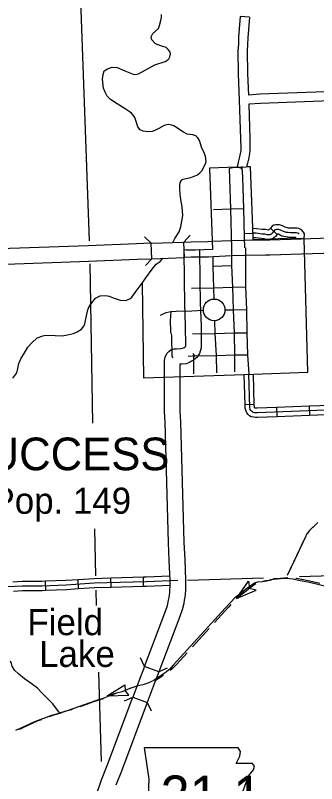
# Model space of a CAD drawing. Extents: x 1164457 to 1439835, y 1590918 to 1773502.
# Drawn here: x 1254222 to 1259097, y 1641151 to 1653578 of the extents above; entities that cross this region are included whole.
import ezdxf

# ---------------------------------------------------------------- set-up
doc = ezdxf.new("R2010")
doc.units = 0
for name, color, linetype in [('Level 10', 7, 'Continuous'), ('Level 21', 7, 'Continuous'), ('Level 24', 7, 'Continuous'), ('Level 32', 7, 'Continuous'), ('Level 33', 7, 'Continuous'), ('Level 34', 7, 'Continuous'), ('Level 35', 7, 'Continuous'), ('Level 37', 7, 'Continuous'), ('Level 43', 7, 'Continuous'), ('Level 46', 7, 'Continuous'), ('Level 5', 7, 'Continuous'), ('Level 6', 7, 'Continuous')]:
    doc.layers.add(name, color=color, linetype=linetype)

msp = doc.modelspace()

# ---------------------------------------------------------------- linework, layer by layer
at = {"layer": 'Level 10'}
for points in [[(1256950, 1649910), (1257059, 1649914), (1257336, 1649919), (1257412, 1649923), (1257714, 1649937), (1257929, 1649944), (1257942, 1649944), (1258271, 1649948), (1258338, 1649949), (1258846, 1649963), (1260259, 1650010), (1260740, 1650032), (1263418, 1650108), (1264752, 1650155), (1264828, 1650158), (1264837, 1649908)], [(1256431, 1649642), (1256422, 1649892), (1256182, 1649884), (1255399, 1649852), (1252701, 1649756)], [(1256422, 1649892), (1256950, 1649910)], [(1264837, 1649908), (1264761, 1649905), (1263426, 1649858), (1260749, 1649782), (1260269, 1649760), (1258853, 1649713), (1258342, 1649699), (1258274, 1649699), (1257944, 1649694), (1257933, 1649694), (1257724, 1649688), (1257425, 1649674), (1257345, 1649669), (1257066, 1649664), (1256958, 1649660), (1256950, 1649910)], [(1256832, 1648186), (1256904, 1648189), (1256945, 1648198), (1256952, 1648203), (1256962, 1648207), (1256970, 1648215), (1256976, 1648223), (1256981, 1648239), (1256977, 1648549), (1256965, 1648923), (1256957, 1649291), (1256952, 1649787), (1257202, 1649790)], [(1257202, 1649790), (1257207, 1649295), (1257215, 1648929), (1257227, 1648554), (1257231, 1648201), (1257201, 1648108), (1257157, 1648046), (1257102, 1647998), (1257073, 1647984), (1257041, 1647964), (1256988, 1647940)], [(1252710, 1649506), (1255408, 1649602), (1256191, 1649634), (1256431, 1649642)], [(1256431, 1649642), (1256958, 1649660)], [(1256309, 1643046), (1256650, 1643939), (1256682, 1644030), (1256701, 1644116), (1256710, 1644161), (1256716, 1644199), (1256721, 1644245), (1256724, 1644285), (1256725, 1644338), (1256725, 1644439), (1256712, 1644767), (1256699, 1645044), (1256644, 1646995), (1256635, 1647167), (1256635, 1647938), (1256636, 1647997), (1256644, 1648047), (1256671, 1648106), (1256703, 1648141), (1256739, 1648168), (1256798, 1648183), (1256832, 1648186)], [(1256988, 1647940), (1256916, 1647937), (1256885, 1647936), (1256885, 1647174), (1256893, 1647005), (1256949, 1645053), (1256962, 1644778), (1256975, 1644444), (1256975, 1644335), (1256974, 1644275), (1256970, 1644223), (1256964, 1644165), (1256956, 1644117), (1256946, 1644064), (1256923, 1643961), (1256884, 1643853), (1256543, 1642957), (1256309, 1643046)], [(1256309, 1643046), (1256218, 1642808), (1256122, 1642551)], [(1256543, 1642957), (1256452, 1642720), (1256356, 1642464)], [(1255613, 1641211), (1255708, 1641443), (1256122, 1642551), (1256356, 1642464)], [(1256356, 1642464), (1255941, 1641352), (1255847, 1641124)], [(1255933, 1634192), (1255683, 1634177), (1255683, 1634182), (1255613, 1636388), (1255540, 1639052), (1255523, 1639608), (1255507, 1640363), (1255498, 1640706), (1255500, 1640783), (1255507, 1640833), (1255508, 1640838), (1255509, 1640872), (1255535, 1640977), (1255613, 1641211)]]:
    msp.add_lwpolyline(points, dxfattribs=at)
at = {"layer": 'Level 21'}
msp.add_lwpolyline([(1256307, 1641730), (1256383, 1641222), (1256349, 1640452), (1256417, 1640410), (1256544, 1640410), (1256544, 1640139), (1257610, 1640139), (1257661, 1640249), (1257644, 1640427), (1257669, 1640630), (1257762, 1640791), (1257821, 1640909), (1257906, 1641036), (1257957, 1641171), (1257999, 1641281), (1258075, 1641374), (1258092, 1641434), (1258058, 1641476), (1257796, 1641476), (1257855, 1641594), (1257864, 1641670), (1257829, 1641729)], close=True, dxfattribs=at)
at = {"layer": 'Level 24'}
msp.add_circle((1257439, 1648813), 175, dxfattribs=at)
at = {"layer": 'Level 32'}
for p, q in [((1258348, 1650138), (1258457, 1650035)), ((1258897, 1649964), (1258762, 1649961)), ((1258088, 1647284), (1257938, 1647280)), ((1258446, 1647234), (1258452, 1647084)), ((1258974, 1647254), (1258980, 1647104)), ((1255770, 1644330), (1255766, 1644480)), ((1256298, 1644345), (1256294, 1644495)), ((1254716, 1644280), (1254710, 1644430)), ((1255245, 1644305), (1255236, 1644455))]:
    msp.add_line(p, q, dxfattribs=at)
for points in [[(1258897, 1649964), (1258901, 1650044), (1258887, 1650071), (1258851, 1650106), (1258842, 1650112), (1258829, 1650120), (1258809, 1650128), (1258777, 1650135), (1258753, 1650136), (1258737, 1650136), (1258677, 1650136), (1258644, 1650138), (1258625, 1650141), (1258586, 1650150), (1258544, 1650172), (1258527, 1650179), (1258496, 1650189), (1258461, 1650191), (1258437, 1650189), (1258407, 1650182), (1258379, 1650168), (1258348, 1650138), (1258316, 1650101)], [(1258345, 1649954), (1258330, 1649953), (1258312, 1649952), (1258287, 1649953), (1258250, 1649963), (1258220, 1649964), (1258199, 1649966), (1258111, 1649978), (1258068, 1649979), (1258062, 1650129)], [(1258316, 1650101), (1258272, 1650112), (1258231, 1650114), (1258216, 1650115), (1258123, 1650127), (1258062, 1650129)], [(1258815, 1650038), (1258803, 1650048), (1258801, 1650050), (1258796, 1650053), (1258788, 1650056), (1258768, 1650060), (1258751, 1650061), (1258737, 1650061), (1258675, 1650061), (1258636, 1650063), (1258611, 1650067), (1258560, 1650079), (1258511, 1650104), (1258500, 1650109), (1258482, 1650115), (1258462, 1650116), (1258449, 1650115), (1258433, 1650111), (1258423, 1650106), (1258403, 1650087), (1258375, 1650054), (1258360, 1650038), (1258343, 1650030), (1258323, 1650027), (1258312, 1650027), (1258299, 1650028)], [(1258299, 1650028), (1258261, 1650037), (1258225, 1650039), (1258208, 1650041), (1258117, 1650052), (1258067, 1650054)], [(1258762, 1649961), (1258762, 1649985), (1258759, 1649985), (1258749, 1649986), (1258736, 1649986), (1258673, 1649986), (1258629, 1649988), (1258597, 1649993), (1258534, 1650008), (1258478, 1650037), (1258472, 1650039), (1258469, 1650040), (1258463, 1650041), (1258457, 1650035), (1258431, 1650003), (1258405, 1649977), (1258365, 1649957), (1258345, 1649954)], [(1257938, 1647280), (1257923, 1647771), (1258073, 1647776)], [(1259922, 1647216), (1258140, 1647147), (1258114, 1647147), (1258093, 1647150), (1258069, 1647156), (1258057, 1647164), (1258041, 1647176), (1258033, 1647187), (1258024, 1647202), (1258015, 1647235), (1257998, 1647773)], [(1258088, 1647284), (1258073, 1647776)], [(1258452, 1647084), (1258142, 1647072), (1258109, 1647072), (1258079, 1647076), (1258039, 1647086), (1258013, 1647102), (1257988, 1647123), (1257970, 1647146), (1257955, 1647173), (1257940, 1647224), (1257938, 1647280)], [(1258446, 1647234), (1258137, 1647222), (1258118, 1647222), (1258108, 1647223), (1258099, 1647226), (1258095, 1647229), (1258094, 1647231), (1258089, 1647247), (1258088, 1647284)], [(1258974, 1647254), (1258446, 1647234)], [(1259501, 1647275), (1258974, 1647254)], [(1258980, 1647104), (1258452, 1647084)], [(1259507, 1647125), (1258980, 1647104)], [(1255236, 1644455), (1255495, 1644471), (1255766, 1644480)], [(1255766, 1644480), (1256294, 1644495)], [(1256294, 1644495), (1256338, 1644497), (1256722, 1644512)], [(1251548, 1644222), (1251717, 1644226), (1251976, 1644232), (1253539, 1644311), (1254100, 1644337), (1254336, 1644348), (1254651, 1644352), (1255043, 1644367), (1255498, 1644397), (1256340, 1644422), (1256850, 1644442)], [(1254182, 1644416), (1254334, 1644423), (1254649, 1644427), (1254710, 1644430)], [(1254710, 1644430), (1255039, 1644442), (1255236, 1644455)], [(1255770, 1644330), (1256298, 1644345)], [(1256298, 1644345), (1256343, 1644347), (1256725, 1644362)], [(1254189, 1644266), (1254338, 1644273), (1254653, 1644277), (1254716, 1644280)], [(1254716, 1644280), (1255047, 1644292), (1255245, 1644305)], [(1255245, 1644305), (1255502, 1644322), (1255770, 1644330)]]:
    msp.add_lwpolyline(points, dxfattribs=at)
at = {"layer": 'Level 33'}
for points in [[(1257682, 1651097), (1257703, 1650450), (1257719, 1649812)], [(1257719, 1649812), (1257722, 1649530), (1257736, 1649179), (1257747, 1648814), (1257761, 1648440), (1257770, 1648087)], [(1257419, 1649671), (1257420, 1649519), (1257428, 1649173), (1257433, 1648988)], [(1257072, 1649165), (1257428, 1649173), (1257736, 1649179), (1257948, 1649184)], [(1257614, 1648814), (1257747, 1648814), (1257960, 1648818)], [(1257960, 1648818), (1257966, 1648440), (1257978, 1648089), (1257998, 1647773)], [(1256573, 1648727), (1256660, 1648769), (1256713, 1648784), (1256742, 1648787), (1256825, 1648791), (1257078, 1648799), (1257264, 1648807)], [(1256742, 1648787), (1256735, 1648765), (1256731, 1648745), (1256731, 1648731), (1256730, 1648698), (1256729, 1648653), (1256731, 1648456), (1256736, 1648436), (1256741, 1648429), (1256745, 1648420), (1256748, 1648398), (1256750, 1648374), (1256755, 1648071), (1256761, 1648055), (1256776, 1648036)], [(1257445, 1648638), (1257452, 1648434), (1257470, 1648077)], [(1257089, 1648426), (1257452, 1648434), (1257761, 1648440), (1257966, 1648440)], [(1257016, 1648065), (1257090, 1648068), (1257105, 1648068), (1257132, 1648068), (1257470, 1648077), (1257770, 1648087), (1257978, 1648089)], [(1257094, 1648115), (1257107, 1648092), (1257113, 1648084), (1257118, 1648078), (1257132, 1648068)]]:
    msp.add_lwpolyline(points, dxfattribs=at)
at = {"layer": 'Level 34'}
for points in [[(1257882, 1651099), (1257872, 1651106), (1257855, 1651111), (1257832, 1651115), (1257796, 1651116), (1257769, 1651116), (1257743, 1651113), (1257728, 1651110), (1257709, 1651105), (1257682, 1651097)], [(1257882, 1651099), (1257887, 1651085), (1257890, 1651068), (1257893, 1651047), (1257899, 1650957), (1257916, 1650453), (1257927, 1649985), (1257931, 1649819)], [(1257889, 1651132), (1257887, 1651085)], [(1257428, 1650435), (1257703, 1650450), (1257911, 1650452)], [(1257925, 1650048), (1258065, 1650054)], [(1257945, 1649819), (1257946, 1649701), (1257947, 1649550), (1257948, 1649184), (1257960, 1648818)], [(1257420, 1649519), (1257722, 1649530)], [(1257105, 1648068), (1257106, 1647782)], [(1257470, 1648077), (1257478, 1647796)], [(1257770, 1648087), (1257770, 1647813)]]:
    msp.add_lwpolyline(points, dxfattribs=at)
at = {"layer": 'Level 35'}
for points in [[(1256770, 1649904), (1256804, 1649966), (1256870, 1650075), (1256902, 1650156), (1256933, 1650338), (1256922, 1650483), (1256897, 1650597), (1256888, 1650687), (1256885, 1650772), (1256883, 1650824), (1256888, 1650875), (1256915, 1650918), (1256937, 1650929), (1257010, 1650944), (1257062, 1650957), (1257169, 1650996), (1257206, 1651028), (1257241, 1651065), (1257298, 1651175), (1257307, 1651215), (1257301, 1651293), (1257274, 1651372), (1257238, 1651427), (1257204, 1651551), (1257172, 1651598), (1257140, 1651630), (1257092, 1651647), (1257047, 1651651), (1257000, 1651658), (1256942, 1651686), (1256784, 1651790), (1256753, 1651799), (1256693, 1651811), (1256628, 1651795), (1256543, 1651745), (1256480, 1651713), (1256433, 1651700), (1256360, 1651693), (1256291, 1651705), (1256240, 1651726), (1256203, 1651774), (1256181, 1651845), (1256153, 1651928), (1256129, 1651964), (1256100, 1651993), (1256061, 1652025), (1255997, 1652066), (1255868, 1652148), (1255762, 1652218), (1255707, 1652273), (1255675, 1652335), (1255650, 1652399), (1255633, 1652543), (1255642, 1652622), (1255657, 1652678), (1255713, 1652715), (1255786, 1652740), (1255871, 1652733), (1255995, 1652683), (1256126, 1652626), (1256155, 1652621), (1256214, 1652631), (1256481, 1652780), (1256645, 1652833), (1256688, 1652859), (1256707, 1652873), (1256723, 1652908), (1256732, 1652953), (1256721, 1652995), (1256697, 1653025), (1256662, 1653056), (1256593, 1653080), (1256514, 1653106), (1256485, 1653124), (1256430, 1653180), (1256422, 1653228), (1256446, 1653284), (1256536, 1653365), (1256556, 1653414), (1256570, 1653475), (1256586, 1653543), (1256587, 1653594)], [(1256434, 1649475), (1256503, 1649551), (1256563, 1649596), (1256607, 1649648)], [(1254183, 1647709), (1254248, 1647796), (1254259, 1647867), (1254279, 1647945), (1254316, 1648033), (1254362, 1648109), (1254421, 1648210), (1254488, 1648283), (1254577, 1648359), (1254664, 1648395), (1254712, 1648406), (1254868, 1648399), (1254981, 1648395), (1255067, 1648409), (1255164, 1648433), (1255222, 1648458), (1255292, 1648503), (1255330, 1648552), (1255346, 1648590), (1255364, 1648668), (1255395, 1648813), (1255417, 1648871), (1255457, 1648927), (1255519, 1649002), (1255594, 1649039), (1255686, 1649046), (1255738, 1649033), (1255823, 1649001), (1255917, 1648972), (1256005, 1648965), (1256073, 1648994), (1256104, 1649018), (1256161, 1649095), (1256276, 1649244), (1256335, 1649330), (1256434, 1649475)], [(1254940, 1642285), (1254927, 1642310), (1254890, 1642360), (1254830, 1642442), (1254743, 1642528), (1254652, 1642622), (1254579, 1642694), (1254475, 1642768), (1254367, 1642847), (1254277, 1642919), (1254207, 1642985), (1254172, 1643049), (1254157, 1643095), (1254143, 1643133)]]:
    msp.add_lwpolyline(points, dxfattribs=at)
at = {"layer": 'Level 37'}
for points in [[(1256313, 1649995), (1256422, 1649892)], [(1256950, 1649910), (1257052, 1650020)], [(1256431, 1649642), (1256328, 1649533)], [(1256958, 1649660), (1256958, 1649660)], [(1256309, 1643046), (1256248, 1643183)], [(1256680, 1643018), (1256543, 1642957)], [(1255986, 1642489), (1256122, 1642551)], [(1256356, 1642464), (1256419, 1642327)]]:
    msp.add_lwpolyline(points, dxfattribs=at)
at = {"layer": 'Level 43'}
for p, q in [((1257802, 1644144), (1257997, 1644427)), ((1257997, 1644427), (1258009, 1644309)), ((1257802, 1644144), (1258118, 1644278)), ((1258118, 1644278), (1258009, 1644309)), ((1255706, 1642571), (1255991, 1642749)), ((1255991, 1642749), (1256001, 1642658)), ((1256056, 1642584), (1256001, 1642657)), ((1255706, 1642571), (1256056, 1642584))]:
    msp.add_line(p, q, dxfattribs=at)
for points in [[(1259117, 1645377), (1258984, 1645244), (1258943, 1645195), (1258929, 1645173), (1258921, 1645153), (1258622, 1644516)], [(1259071, 1645330), (1258984, 1645244), (1258943, 1645195), (1258929, 1645173), (1258921, 1645153), (1258852, 1645006)], [(1258796, 1644887), (1258627, 1644528)], [(1260191, 1644115), (1258981, 1644404), (1258801, 1644439), (1258716, 1644456), (1258659, 1644463), (1258616, 1644467), (1258572, 1644467), (1258461, 1644458), (1258357, 1644447), (1258285, 1644425), (1258222, 1644416), (1258140, 1644407), (1258091, 1644392), (1258026, 1644348), (1257947, 1644290), (1257870, 1644224), (1257776, 1644157), (1257706, 1644087), (1257618, 1643991), (1256834, 1643131), (1256774, 1643066), (1256714, 1642999), (1256675, 1642967), (1256646, 1642944), (1256599, 1642912), (1256551, 1642878), (1256508, 1642850), (1256461, 1642820), (1256368, 1642777), (1256282, 1642751), (1256186, 1642726), (1256076, 1642687), (1255950, 1642638), (1255857, 1642612), (1255830, 1642605), (1255790, 1642584), (1255735, 1642563), (1255655, 1642533), (1255521, 1642488)], [(1258629, 1644480), (1258625, 1644480), (1258515, 1644471), (1258411, 1644461), (1258339, 1644438), (1258275, 1644429), (1258239, 1644425)], [(1259149, 1644390), (1259035, 1644417), (1258855, 1644452), (1258770, 1644470), (1258761, 1644471)], [(1258115, 1644385), (1258079, 1644361), (1258001, 1644303), (1257957, 1644266)], [(1257957, 1644266), (1257802, 1644144)], [(1257711, 1644048), (1257671, 1644004), (1257444, 1643756)], [(1257356, 1643658), (1257089, 1643365)], [(1257000, 1643268), (1256888, 1643144), (1256827, 1643080), (1256767, 1643012), (1256729, 1642981), (1256728, 1642980)], [(1256621, 1642903), (1256605, 1642892), (1256562, 1642863), (1256489, 1642817)], [(1256083, 1642690), (1256076, 1642687), (1255950, 1642638), (1255857, 1642612), (1255706, 1642571)], [(1255521, 1642488), (1255334, 1642425), (1255076, 1642333), (1255012, 1642314), (1254962, 1642302), (1254887, 1642272), (1254804, 1642251), (1254534, 1642150), (1254378, 1642082), (1254302, 1642044), (1254264, 1642026), (1254222, 1642011)], [(1255641, 1642524), (1255575, 1642502), (1255454, 1642461)], [(1255142, 1642351), (1255130, 1642347), (1255065, 1642327), (1255016, 1642315), (1254940, 1642285), (1254858, 1642265), (1254766, 1642230)], [(1255454, 1642461), (1255387, 1642438), (1255267, 1642395)], [(1254642, 1642184), (1254588, 1642164), (1254432, 1642096), (1254355, 1642057), (1254317, 1642039), (1254279, 1642026)]]:
    msp.add_lwpolyline(points, dxfattribs=at)
at = {"layer": 'Level 46'}
for points in [[(1258009, 1653547), (1257859, 1653557), (1257845, 1653359), (1257834, 1653223), (1257831, 1653114), (1257824, 1653010), (1257829, 1652632), (1257846, 1652207), (1257865, 1651581), (1257868, 1651433), (1257868, 1651394), (1257865, 1651367), (1257854, 1651315), (1257848, 1651291), (1257825, 1651202), (1257820, 1651178), (1257811, 1651121), (1257964, 1651126)], [(1258009, 1653547), (1257995, 1653347), (1257984, 1653215), (1257980, 1653107), (1257974, 1653006), (1257979, 1652636), (1257993, 1652289)], [(1260597, 1652391), (1258180, 1652301), (1257993, 1652289)], [(1260604, 1652242), (1258188, 1652151), (1257998, 1652139)], [(1257998, 1652139), (1258015, 1651585), (1258018, 1651434), (1258018, 1651384), (1258013, 1651343), (1258000, 1651281), (1257993, 1651254), (1257971, 1651167), (1257967, 1651150), (1257964, 1651126)]]:
    msp.add_lwpolyline(points, dxfattribs=at)
at = {"layer": 'Level 5'}
for points in [[(1255420, 1649930), (1255234, 1655159)], [(1255477, 1646979), (1255430, 1649557)], [(1255522, 1644513), (1255509, 1645270)], [(1257010, 1644440), (1258235, 1644480)], [(1258822, 1644499), (1260916, 1644568)], [(1255536, 1644032), (1255528, 1644279)], [(1255617, 1641511), (1255570, 1642954)]]:
    msp.add_lwpolyline(points, dxfattribs=at)
at = {"layer": 'Level 6'}
for points in [[(1257799, 1651121), (1257363, 1651108), (1257411, 1649789), (1256993, 1649775)], [(1258026, 1651128), (1257973, 1651126)], [(1258062, 1650143), (1258026, 1651128)], [(1258755, 1649973), (1258069, 1649946), (1258068, 1649973)], [(1258956, 1647806), (1258897, 1649964)], [(1256275, 1649242), (1256298, 1647716)], [(1256298, 1647716), (1257923, 1647771)], [(1258073, 1647776), (1258956, 1647806)]]:
    msp.add_lwpolyline(points, dxfattribs=at)

# ---------------------------------------------------------------- texts
at = {"layer": 'Level 21'}
msp.add_text('21 1', height=633, dxfattribs=at).set_placement((1256571, 1640649))
at = {"layer": 'Level 35'}
for s, p in [('Field', (1254416, 1643552)), ('Lake', (1254606, 1643038))]:
    msp.add_text(s, height=422.4, dxfattribs=at).set_placement(p)
at = {"layer": 'Level 6'}
for s, height, p in [('SUCCESS', 528, (1253302, 1646220)), ('Pop. 149', 422, (1253836, 1645516))]:
    msp.add_text(s, height=height, dxfattribs=at).set_placement(p)

doc.saveas('drawing.dxf')
